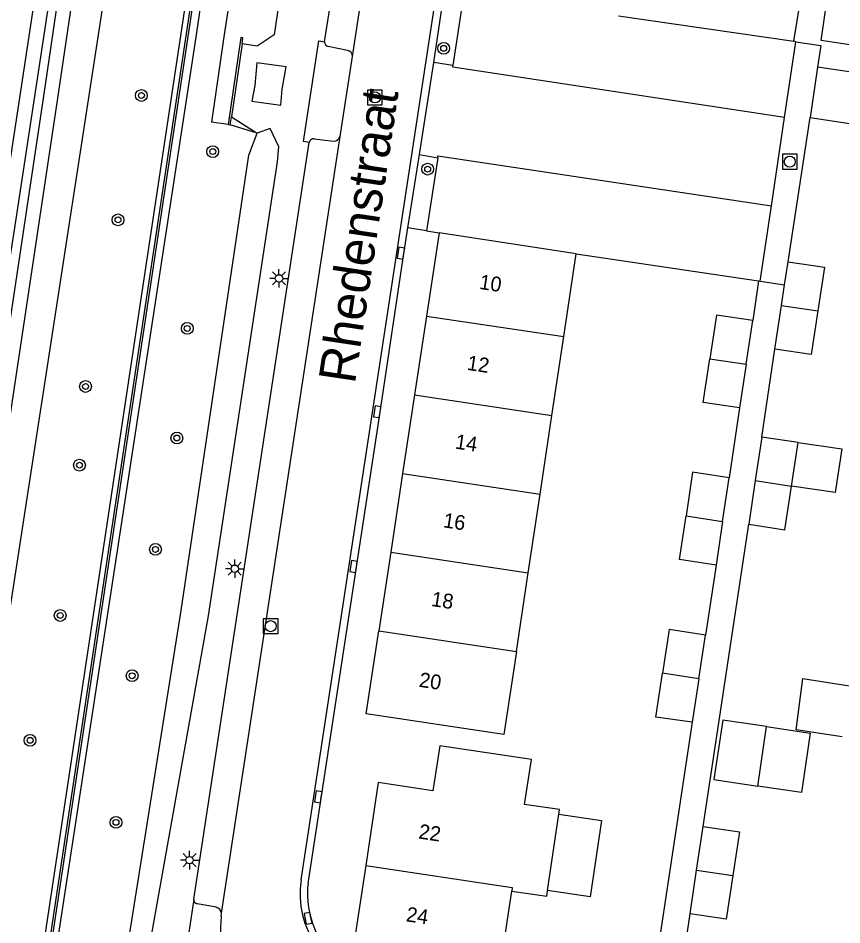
# Model space of a CAD drawing. Extents: x 124000 to 128010, y 398999 to 403000.
# Drawn here: x 126361 to 126416.8, y 399876.2 to 399937.7 of the extents above; entities that cross this region are included whole.
import ezdxf

# ---------------------------------------------------------------- set-up
doc = ezdxf.new("R2010")
doc.units = 0
for name, color, linetype in [('gg-afsc-erfafscheiding', 7, 'Continuous'), ('gg-afsc-geluidsscherm', 7, 'Continuous'), ('gg-afsc-hekwerk', 7, 'Continuous'), ('gg-anno-huisnummerreeks BGT', 7, 'Continuous'), ('gg-anno-openbare ruimte label', 7, 'Continuous'), ('gg-bbg-bijgebouw', 7, 'Continuous'), ('gg-bbg-gedigitaliseerde bijgebouw', 7, 'Continuous'), ('gg-bbg-hoofdgebouw', 7, 'Continuous'), ('gg-bbg-lage trafo', 7, 'Continuous'), ('gg-bbg-luifel en loopbrug', 7, 'Continuous'), ('gg-bbg-tussenscheiding', 7, 'Continuous'), ('gg-knt-BGT kruinlijn', 7, 'Continuous'), ('gg-knt-bovenkant onderkant talud', 7, 'Continuous'), ('gg-knt-verharding', 7, 'Continuous'), ('gg-knt-verharding nz', 7, 'Continuous'), ('gg-kntw-bovenkant insteek waterloop', 7, 'Continuous'), ('gg-kntw-waterlijn', 7, 'Continuous'), ('gg-kwrk-keermuur', 7, 'Continuous'), ('gt-grn-groengrens', 7, 'Continuous'), ('gt-grn-weggrens', 7, 'Continuous'), ('gt-symb-boom', 7, 'Continuous'), ('gt-symb-kolk', 7, 'Continuous'), ('gt-symb-lichtmast', 7, 'Continuous'), ('gt-symb-rioolschacht', 7, 'Continuous')]:
    doc.layers.add(name, color=color, linetype=linetype)

# ---------------------------------------------------------------- blocks, each defined once
blk = doc.blocks.new('gt0-RS')
at = {"layer": 'gt-symb-rioolschacht'}
blk.add_lwpolyline([(-0.5, -0.5), (0.5, -0.5), (0.5, 0.5), (-0.5, 0.5)], close=True, dxfattribs=at)
blk.add_circle((0, 0), 0.375, dxfattribs=at)
blk = doc.blocks.new('gt0-BOOM')
at = {"layer": 'gt-symb-boom'}
for radius in [0.4, 0.2]:
    blk.add_circle((0, 0), radius, dxfattribs=at)
blk = doc.blocks.new('gt0-LMAST')
at = {"layer": 'gt-symb-lichtmast'}
for p, q in [((-0.005, 0.246), (-0.005, 0.621)), ((-0.182, 0.173), (-0.447, 0.438)), ((0.172, 0.173), (0.437, 0.438)), ((-0.255, -0.004), (-0.63, -0.004)), ((-0.182, -0.181), (-0.447, -0.446)), ((-0.005, -0.254), (-0.005, -0.629)), ((0.437, -0.446), (0.172, -0.181)), ((0.245, -0.004), (0.62, -0.004))]:
    blk.add_line(p, q, dxfattribs=at)
blk.add_circle((-0.005, -0.004), 0.25, dxfattribs=at)
blk = doc.blocks.new('gt0-KOLK')
at = {"layer": 'gt-symb-kolk'}
blk.add_lwpolyline([(0, 0), (0.375, 0), (0.375, 0.4), (-0.375, 0.4), (-0.375, 0), (0, 0)], dxfattribs=at)

msp = doc.modelspace()

# ---------------------------------------------------------------- linework, layer by layer
at = {"layer": 'gg-afsc-erfafscheiding'}
msp.add_line((126388.653, 399923.298), (126387.385, 399923.498), dxfattribs=at)
at = {"layer": 'gg-afsc-geluidsscherm'}
for points in [[(126433.522, 399396.193), (126294.266, 399417.89), (126294.312, 399418.568), (126384.69, 400018.495), (126392.393, 400081.874), (126401.389, 400173.179), (126405.812, 400237.067), (126415.183, 400254.387), (126416.933, 400270.191), (126421.505, 400378.061), (126422.448, 400394.046), (126423.962, 400411.149), (126518.093, 400411.476), (126531.613, 400399.449), (126531.513, 400399.337)], [(126433.522, 399396.193), (126433.545, 399396.341), (126294.438, 399418.015), (126294.46, 399418.546), (126384.838, 400018.472), (126392.542, 400081.856), (126401.538, 400173.164), (126405.962, 400237.057), (126415.315, 400254.315), (126417.082, 400270.175), (126421.655, 400378.055), (126422.598, 400394.037), (126424.098, 400410.986), (126518.093, 400411.326), (126531.513, 400399.337)]]:
    msp.add_lwpolyline(points, dxfattribs=at)
at = {"layer": 'gg-afsc-hekwerk'}
for p, q in [((126413.559, 399936.159), (126413.998, 399938.787)), ((126401.666, 399937.885), (126413.559, 399936.159)), ((126413.172, 399921.201), (126414.677, 399930.998)), ((126398.808, 399921.75), (126411.169, 399919.903)), ((126411.169, 399919.903), (126410.776, 399917.224)), ((126411.394, 399909.319), (126412.278, 399915.278)), ((126409.886, 399911.3), (126409.166, 399906.555)), ((126407.415, 399882.902), (126410.498, 399903.396)), ((126408.283, 399900.633), (126407.559, 399895.885)), ((126406.665, 399889.966), (126404.519, 399875.736))]:
    msp.add_line(p, q, dxfattribs=at)
for points in [[(126422.571, 399935.141), (126415.408, 399936.222), (126417.169, 399948.374)], [(126404.519, 399875.736), (126406.297, 399875.469), (126406.525, 399876.984)]]:
    msp.add_lwpolyline(points, dxfattribs=at)
at = {"layer": 'gg-bbg-bijgebouw'}
for p, q in [((126412.936, 399919.64), (126413.172, 399921.201)), ((126412.725, 399918.24), (126412.936, 399919.64)), ((126412.278, 399915.278), (126412.725, 399918.24)), ((126410.331, 399914.262), (126410.776, 399917.224)), ((126410.331, 399914.262), (126409.886, 399911.3)), ((126411.394, 399909.319), (126410.946, 399906.358)), ((126413.847, 399908.948), (126411.394, 399909.319)), ((126413.399, 399905.987), (126413.847, 399908.948)), ((126408.725, 399903.594), (126409.166, 399906.555)), ((126410.946, 399906.358), (126410.498, 399903.396)), ((126408.725, 399903.594), (126408.283, 399900.633)), ((126407.112, 399892.926), (126407.559, 399895.885)), ((126407.112, 399892.926), (126406.665, 399889.966)), ((126406.97, 399879.943), (126407.415, 399882.902)), ((126406.525, 399876.984), (126406.97, 399879.943))]:
    msp.add_line(p, q, dxfattribs=at)
for points in [[(126413.172, 399921.201), (126415.63, 399920.83), (126415.183, 399917.869)], [(126415.183, 399917.869), (126414.736, 399914.907), (126412.278, 399915.278)], [(126410.776, 399917.224), (126408.309, 399917.587), (126407.865, 399914.629)], [(126409.886, 399911.3), (126407.42, 399911.671), (126407.865, 399914.629)], [(126409.166, 399906.555), (126406.698, 399906.923), (126406.257, 399903.962)], [(126410.498, 399903.396), (126412.951, 399903.025), (126413.399, 399905.987)], [(126408.283, 399900.633), (126405.815, 399901.001), (126406.257, 399903.962)], [(126407.559, 399895.885), (126405.104, 399896.256), (126404.656, 399893.291)], [(126406.665, 399889.966), (126404.208, 399890.326), (126404.656, 399893.291)], [(126416.828, 399888.985), (126413.71, 399889.466), (126414.174, 399892.93), (126417.326, 399892.444)], [(126407.415, 399882.902), (126409.877, 399882.529), (126409.429, 399879.571)], [(126409.429, 399879.571), (126408.981, 399876.612), (126406.525, 399876.984)]]:
    msp.add_lwpolyline(points, dxfattribs=at)
at = {"layer": 'gg-bbg-gedigitaliseerde bijgebouw'}
msp.add_line((126411.11, 399885.644), (126411.71, 399889.671), dxfattribs=at)
msp.add_lwpolyline([(126411.71, 399889.671), (126408.747, 399890.112), (126408.146, 399886.085), (126411.11, 399885.644)], dxfattribs=at)
at = {"layer": 'gg-bbg-hoofdgebouw'}
for p, q in [((126389.502, 399923.169), (126388.647, 399917.526)), ((126398.808, 399921.75), (126389.502, 399923.169)), ((126397.962, 399916.126), (126398.808, 399921.75)), ((126388.647, 399917.526), (126387.839, 399912.187)), ((126397.158, 399910.786), (126397.962, 399916.126)), ((126387.839, 399912.187), (126387.03, 399906.848)), ((126396.354, 399905.446), (126397.158, 399910.786)), ((126387.03, 399906.848), (126386.221, 399901.509)), ((126395.55, 399900.106), (126396.354, 399905.446)), ((126386.221, 399901.509), (126385.412, 399896.17)), ((126394.747, 399894.766), (126395.55, 399900.106)), ((126396.864, 399878.558), (126397.631, 399883.737))]:
    msp.add_line(p, q, dxfattribs=at)
for points in [[(126394.747, 399894.766), (126393.901, 399889.147), (126384.561, 399890.55), (126385.412, 399896.17)], [(126397.631, 399883.737), (126397.677, 399884.045), (126395.303, 399884.402), (126395.776, 399887.438), (126389.545, 399888.38), (126389.072, 399885.327), (126385.38, 399885.877), (126384.532, 399880.254)], [(126384.532, 399880.254), (126383.685, 399874.641), (126387.525, 399874.062), (126387.414, 399873.328), (126391.522, 399872.712), (126391.638, 399873.441), (126393.62, 399873.161), (126394.432, 399878.512)], [(126394.432, 399878.512), (126396.807, 399878.17), (126396.864, 399878.558)]]:
    msp.add_lwpolyline(points, dxfattribs=at)
at = {"layer": 'gg-bbg-lage trafo'}
msp.add_lwpolyline([(126376.793, 399932.108), (126378.773, 399931.832), (126378.859, 399932.918), (126379.14, 399934.434), (126377.143, 399934.692), (126377.008, 399933.171), (126376.793, 399932.108)], dxfattribs=at)
at = {"layer": 'gg-bbg-luifel en loopbrug'}
for p, q in [((126415.168, 399934.411), (126414.677, 399930.998)), ((126420.378, 399933.619), (126415.168, 399934.411)), ((126414.677, 399930.998), (126419.853, 399930.203))]:
    msp.add_line(p, q, dxfattribs=at)
for points in [[(126413.847, 399908.948), (126416.811, 399908.506), (126416.369, 399905.544), (126413.399, 399905.987)], [(126411.71, 399889.671), (126414.673, 399889.229), (126414.073, 399885.202), (126411.11, 399885.644)], [(126397.631, 399883.737), (126400.511, 399883.31), (126399.744, 399878.132), (126396.864, 399878.558)]]:
    msp.add_lwpolyline(points, dxfattribs=at)
at = {"layer": 'gg-bbg-tussenscheiding'}
for p, q in [((126412.725, 399918.24), (126415.183, 399917.869)), ((126388.647, 399917.526), (126397.962, 399916.126)), ((126407.865, 399914.629), (126410.331, 399914.262)), ((126387.839, 399912.187), (126397.158, 399910.786)), ((126387.03, 399906.848), (126396.354, 399905.446)), ((126410.946, 399906.358), (126413.399, 399905.987)), ((126406.257, 399903.962), (126408.725, 399903.594)), ((126386.221, 399901.509), (126395.55, 399900.106)), ((126385.412, 399896.17), (126394.747, 399894.766)), ((126407.112, 399892.926), (126404.656, 399893.291)), ((126406.97, 399879.943), (126409.429, 399879.571))]:
    msp.add_line(p, q, dxfattribs=at)
msp.add_lwpolyline([(126384.532, 399880.254), (126394.469, 399878.76), (126394.432, 399878.512)], dxfattribs=at)
at = {"layer": 'gg-knt-BGT kruinlijn'}
for points in [[(126300.242, 399460.061), (126317.155, 399573.618), (126327.853, 399643.472), (126345.991, 399764.256), (126377.209, 399971.201), (126384.168, 400018.601), (126391.597, 400079.17), (126401.015, 400171.969), (126405.272, 400237.075), (126405.836, 400239.447)], [(126405.997, 400230.826), (126401.252, 400165.313), (126397.513, 400125.164), (126394.977, 400098.805), (126384.91, 400016.956), (126372.958, 399936.144), (126361.724, 399862.808), (126350.889, 399790.817), (126334.29, 399679.75), (126332.168, 399665.424)]]:
    msp.add_lwpolyline(points, dxfattribs=at)
at = {"layer": 'gg-knt-bovenkant onderkant talud'}
for p, q in [((126375.414, 399931.028), (126377.154, 399929.924)), ((126377.154, 399929.924), (126375.337, 399930.497))]:
    msp.add_line(p, q, dxfattribs=at)
for points in [[(126293.229, 399462.196), (126310.804, 399577.419), (126321.785, 399641.664), (126324.83, 399661.281), (126341.384, 399769.192), (126355.148, 399863.606), (126371.991, 399972.892), (126378.989, 400019.753), (126385.648, 400077.466), (126395.494, 400171.208), (126398.482, 400218.678), (126399.195, 400237.176), (126399.855, 400244.875), (126401.075, 400247.387), (126403.954, 400253.411), (126406.57, 400258.304), (126407.848, 400260.608), (126408.109, 400271.651), (126414.004, 400375.395), (126416.291, 400410.556)], [(126410.026, 400201.252), (126406.945, 400166.33), (126403.502, 400125.401), (126400.753, 400098.856), (126390.168, 400016.966), (126378.327, 399936.59), (126377.163, 399935.839), (126376.138, 399935.989)]]:
    msp.add_lwpolyline(points, dxfattribs=at)
at = {"layer": 'gg-knt-verharding'}
for p, q in [((126381.737, 399936.135), (126385.828, 399962.779)), ((126380.151, 399879.284), (126392.202, 399958.322)), ((126389.135, 399934.724), (126389.873, 399939.692)), ((126391.179, 399939.498), (126390.435, 399934.521)), ((126383.294, 399935.54), (126381.984, 399935.809)), ((126382.8, 399929.712), (126383.63, 399935.13)), ((126388.172, 399928.48), (126389.135, 399934.724)), ((126390.435, 399934.521), (126389.135, 399934.724)), ((126381.028, 399929.549), (126382.341, 399929.391)), ((126372.863, 399877.962), (126380.695, 399929.293)), ((126387.385, 399923.498), (126388.172, 399928.48)), ((126388.172, 399928.48), (126389.406, 399928.264)), ((126389.406, 399928.264), (126388.653, 399923.298)), ((126388.653, 399923.298), (126389.502, 399923.169)), ((126372.863, 399877.962), (126371.402, 399868.269)), ((126374.394, 399877.416), (126373.086, 399877.661)), ((126374.717, 399876.801), (126374.747, 399877.024))]:
    msp.add_line(p, q, dxfattribs=at)
for points in [[(126380.695, 399929.293), (126380.308, 399929.367), (126381.338, 399936.201), (126381.737, 399936.135)], [(126380.615, 399879.041), (126385.495, 399911.005), (126387.111, 399921.756), (126387.385, 399923.498)]]:
    msp.add_lwpolyline(points, dxfattribs=at)
for centre, radius, start, end in [((126382.042, 399936.109), 0.306, 175.20077, 259.09937), ((126383.211, 399935.129), 0.419, 0.14342, 78.52665), ((126381.003, 399929.238), 0.312, 85.32534, 169.77857), ((126382.339, 399929.883), 0.492, 270.25215, 339.68161), ((126386.201, 399878.331), 6.125, 171.05006, 259.24235), ((126386.445, 399878.362), 5.87, 173.3567, 196.38581), ((126373.164, 399877.952), 0.301, 178.09312, 254.9737), ((126374.291, 399876.968), 0.459, 6.96894, 77.03778), ((126383.12, 399875.895), 8.452, 173.84963, 251.21089), ((126385.956, 399877.992), 5.3, 194.04393, 268.35695)]:
    msp.add_arc(centre, radius, start, end, dxfattribs=at)
at = {"layer": 'gg-knt-verharding nz'}
for p, q in [((126383.63, 399935.13), (126387.698, 399961.606)), ((126412.93, 399931.003), (126413.695, 399936.122)), ((126413.695, 399936.122), (126413.559, 399936.159)), ((126412.038, 399925.002), (126412.93, 399931.003)), ((126374.747, 399877.024), (126382.8, 399929.712)), ((126411.282, 399919.889), (126412.038, 399925.002)), ((126411.169, 399919.903), (126411.282, 399919.889))]:
    msp.add_line(p, q, dxfattribs=at)
for points in [[(126412.93, 399931.003), (126390.423, 399934.409), (126390.435, 399934.521)], [(126389.406, 399928.264), (126389.416, 399928.397), (126412.038, 399925.002)]]:
    msp.add_lwpolyline(points, dxfattribs=at)
at = {"layer": 'gg-kntw-bovenkant insteek waterloop'}
for points in [[(126323.031, 399662.04), (126321.74, 399660.117), (126320.587, 399660.289), (126320.014, 399662.511), (126332.334, 399743.098), (126336.188, 399768.41), (126344.467, 399823.06), (126353.306, 399883.083), (126359.695, 399923.364), (126365.113, 399959.07), (126369.177, 399986.373), (126372.735, 400012.848), (126375.768, 400035.991), (126379.045, 400062.476), (126382.001, 400085.384), (126384.826, 400114.553), (126387.163, 400137.912), (126389.716, 400166.128), (126391.77, 400193.942), (126393.76, 400220.612), (126395.587, 400247.464), (126396.695, 400267.432)], [(126323.031, 399662.04), (126327.041, 399690.098), (126334.838, 399742.841), (126338.537, 399768.285), (126342.893, 399797.119), (126346.686, 399823.411), (126352.294, 399859.144), (126356.486, 399884.03), (126360.061, 399908.445), (126363.653, 399932.302), (126367.208, 399956.505), (126370.042, 399973.218), (126373.244, 399995.515), (126376.51, 400018.7), (126379.574, 400041.751), (126382.631, 400066.119), (126383.672, 400073.796)], [(126361.845, 399822.703), (126367.901, 399863.704), (126373.865, 399897.184), (126378.548, 399927.987), (126378.623, 399929.011), (126378.049, 399930.253), (126377.154, 399929.924)], [(126337.653, 399672.667), (126358.597, 399810.023), (126360.759, 399823.044), (126366.579, 399863.454), (126372.003, 399897.554), (126376.599, 399928.428), (126377.154, 399929.924)]]:
    msp.add_lwpolyline(points, dxfattribs=at)
at = {"layer": 'gg-kntw-waterlijn'}
for points in [[(126322.073, 399662.408), (126321.351, 399661.331), (126321.033, 399662.562), (126332.954, 399743.212), (126336.808, 399768.525), (126345.446, 399825.528), (126354.295, 399882.932), (126360.683, 399923.211), (126366.102, 399958.921), (126370.167, 399986.233), (126373.726, 400012.716), (126376.76, 400035.865), (126380.037, 400062.351), (126382.262, 400073.983), (126384.138, 400089.122), (126386.6, 400114.4), (126388.846, 400137.708), (126391.398, 400165.952), (126393.748, 400192.659), (126395.378, 400220.459), (126397.199, 400247.7), (126398.164, 400265.142), (126398.387, 400267.099)], [(126396.316, 400215.111), (126394.753, 400190.156), (126392.641, 400165.901), (126390.957, 400143.335), (126388.243, 400118.036), (126385.3, 400093.236), (126381.639, 400066.248), (126378.582, 400041.879), (126375.519, 400018.836), (126372.254, 399995.656), (126369.054, 399973.373), (126366.22, 399956.661), (126362.664, 399932.449), (126359.072, 399908.592), (126355.498, 399884.186), (126351.307, 399859.305), (126345.697, 399823.56), (126341.904, 399797.265), (126337.548, 399768.432), (126333.849, 399742.986), (126326.051, 399690.242), (126322.073, 399662.408)]]:
    msp.add_lwpolyline(points, dxfattribs=at)
at = {"layer": 'gg-kwrk-keermuur'}
for p, q in [((126376.138, 399935.989), (126375.414, 399931.028)), ((126375.337, 399930.497), (126375.414, 399931.028)), ((126375.188, 399930.518), (126375.337, 399930.497))]:
    msp.add_line(p, q, dxfattribs=at)
msp.add_lwpolyline([(126376.138, 399935.989), (126376.198, 399936.399), (126376.05, 399936.421), (126375.188, 399930.518)], dxfattribs=at)
at = {"layer": 'gt-grn-groengrens'}
msp.add_line((126375.188, 399930.518), (126374.058, 399930.683), dxfattribs=at)
msp.add_lwpolyline([(126525.5, 400401.875), (126517.701, 400409.117), (126513.198, 400409.629), (126427.886, 400408.701), (126425.635, 400405.554), (126424.936, 400373.129), (126423.696, 400345.301), (126420.64, 400282.786), (126419.948, 400265.917), (126419.122, 400252.975), (126417.884, 400250.036), (126410.168, 400236.517), (126408.092, 400226.551), (126403.811, 400165.532), (126400.164, 400125.487), (126397.663, 400101.049), (126387.319, 400017.303), (126374.902, 399936.458), (126374.058, 399930.683)], dxfattribs=at)
at = {"layer": 'gt-grn-weggrens'}
msp.add_line((126411.282, 399919.889), (126412.936, 399919.64), dxfattribs=at)
msp.add_lwpolyline([(126413.695, 399936.122), (126415.387, 399935.867), (126415.168, 399934.411)], dxfattribs=at)

# ---------------------------------------------------------------- block references
at = {"layer": 'gt-symb-boom'}
for p in [(126389.815, 399935.685), (126369.312, 399932.488), (126374.149, 399928.68), (126388.725, 399927.491), (126367.725, 399924.049), (126372.421, 399916.686), (126365.522, 399912.749), (126371.716, 399909.249), (126365.113, 399907.409), (126370.264, 399901.695), (126363.805, 399897.214), (126368.683, 399893.125), (126361.76, 399888.742), (126367.591, 399883.178)]:
    msp.add_blockref('gt0-BOOM', p, dxfattribs=at)
at = {"layer": 'gt-symb-kolk'}
for p, rotation in [((126387.111, 399921.756), 81.02989062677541), ((126385.495, 399911.005), 81.45447000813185), ((126383.893, 399900.504), 81.32439220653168), ((126381.51, 399884.882), 81.33236960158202), ((126380.814, 399876.706), 100.65633662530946)]:
    msp.add_blockref('gt0-KOLK', p, dxfattribs=dict(at, rotation=rotation))
at = {"layer": 'gt-symb-lichtmast'}
for p in [(126378.649, 399920.083), (126375.648, 399900.389), (126372.586, 399880.62)]:
    msp.add_blockref('gt0-LMAST', p, dxfattribs=at)
at = {"layer": 'gt-symb-rioolschacht'}
for p in [(126385.152, 399932.354), (126413.287, 399927.996), (126378.078, 399896.487)]:
    msp.add_blockref('gt0-RS', p, dxfattribs=at)

# ---------------------------------------------------------------- texts
at = {"layer": 'gg-anno-huisnummerreeks BGT'}
for s, p in [('10', (126392.186, 399919.37)), ('12', (126391.355, 399913.88)), ('14', (126390.546, 399908.54)), ('16', (126389.737, 399903.201)), ('18', (126388.928, 399897.862)), ('20', (126388.098, 399892.383)), ('22', (126388.068, 399882.091)), ('24', (126387.221, 399876.473))]:
    msp.add_text(s, height=1, rotation=351.4, dxfattribs=at).set_placement(p)
at = {"layer": 'gg-anno-openbare ruimte label'}
msp.add_text('Rhedenstraat', height=2.5, rotation=81.5, dxfattribs=at).set_placement((126383.789, 399912.87))

doc.saveas('drawing.dxf')
